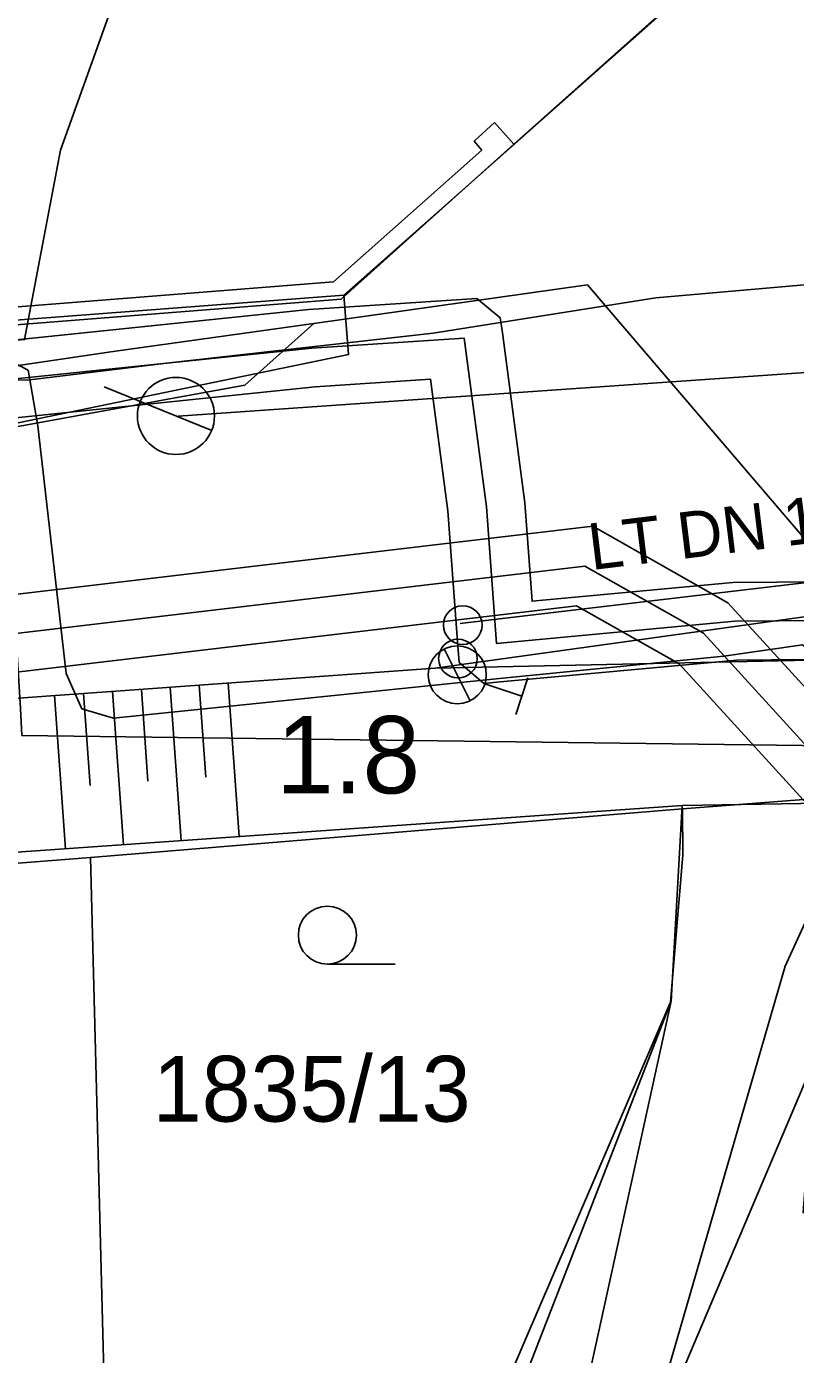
# Model space of a CAD drawing. Extents: x -781083 to -763634, y -1029516 to -1022695.
# Drawn here: x -765279.05 to -765259.17, y -1024370.44 to -1024336.12 of the extents above; entities that cross this region are included whole.
import ezdxf

# ---------------------------------------------------------------- set-up
doc = ezdxf.new("R2010")
doc.units = 0
for name, color, linetype in [('CETIN_chránička', 7, 'Continuous'), ('CETIN_nezaměřený', 7, 'Continuous'), ('CETIN_zaměřený', 7, 'Continuous'), ('GasNet_ochr. pásmo', 7, 'Continuous'), ('GasNet_plyn NTL', 7, 'Continuous'), ('GasNet_plyn STL', 7, 'Continuous'), ('Hranice parcel', 7, 'Continuous'), ('Parcelní čísla', 7, 'Continuous'), ('SVAS_kanalizace', 7, 'Continuous'), ('SVAS_vodovod', 7, 'Continuous'), ('Vnitřní kresba', 7, 'Continuous'), ('Vrstva 17', 7, 'Continuous'), ('Vrstva 41', 7, 'Continuous'), ('Vrstva 43', 7, 'Continuous'), ('Vrstva 48', 7, 'Continuous'), ('Vrstva 49', 7, 'Continuous'), ('Vrstva 51', 7, 'Continuous'), ('Značky kultur', 7, 'Continuous'), ('ČEZd_VN_podzemní', 7, 'Continuous')]:
    doc.layers.add(name, color=color, linetype=linetype)

# ---------------------------------------------------------------- blocks, each defined once
blk = doc.blocks.new('3.04')
at = {"layer": 'Značky kultur'}
blk.add_line((0.07, 0), (17.57, 0), dxfattribs=at)
blk.add_circle((0.07, 7.5), 7.5, dxfattribs=at)
blk = doc.blocks.new('C129_1')
at = {"layer": 'Vrstva 41'}
for p, q in [((-5.01, 17.59), (5, 17.58)), ((0.01, 17.59), (0, 7.51)), ((-5.31, -5.31), (5.31, 5.3))]:
    blk.add_line(p, q, dxfattribs=at)
blk.add_circle((0, 0.01), 7.5, dxfattribs=at)
blk = doc.blocks.new('C130_3')
at = {"layer": 'Vrstva 41'}
blk.add_circle((0, 0), 5, dxfattribs=at)
blk = doc.blocks.new('C138_6')
at = {"layer": 'Vrstva 43'}
blk.add_line((0, 20), (0, -9.96), dxfattribs=at)
blk.add_circle((0, 0), 9.96, dxfattribs=at)

msp = doc.modelspace()

# ---------------------------------------------------------------- linework, layer by layer
at = {"layer": 'CETIN_chránička'}
msp.add_lwpolyline([(-765278.76, -1024346.44), (-765278.03, -1024352.84)], dxfattribs=at)
at = {"layer": 'CETIN_nezaměřený'}
for points in [[(-765279.8, -1024344.26), (-765279.1, -1024344.21), (-765278.17, -1024339.31), (-765274.62, -1024329.4), (-765276.22, -1024328.8)], [(-765233.96, -1024367.52), (-765248.86, -1024367.26), (-765249.36, -1024367.26), (-765249.41, -1024354.76), (-765253.61, -1024354.77), (-765279.17, -1024354.44), (-765279.21, -1024353.74), (-765279.77, -1024344.76), (-765279.8, -1024344.26)]]:
    msp.add_lwpolyline(points, dxfattribs=at)
at = {"layer": 'CETIN_zaměřený'}
for points in [[(-765276.8, -1024353.99), (-765277.62, -1024353.75), (-765278.03, -1024352.84), (-765278.76, -1024346.44), (-765279.01, -1024345), (-765280.13, -1024344.42), (-765283.21, -1024344.71), (-765295.35, -1024345.6)], [(-765243.69, -1024369.24), (-765246.71, -1024370.2), (-765249.23, -1024369.66), (-765253.56, -1024368.44), (-765256.29, -1024367.55), (-765258.97, -1024366.77), (-765258.35, -1024358.4), (-765257.99, -1024355.91), (-765258.18, -1024352.73), (-765258.99, -1024352.1), (-765261.02, -1024352.39), (-765266.91, -1024352.98), (-765276.8, -1024353.99)]]:
    msp.add_lwpolyline(points, dxfattribs=at)
at = {"layer": 'GasNet_ochr. pásmo'}
for points in [[(-765296.108, -1024345.951), (-765271.754, -1024343.433), (-765267.806, -1024343.172), (-765267.412, -1024343.146), (-765266.801, -1024343.646), (-765266.749, -1024344.038), (-765266.165, -1024348.427), (-765265.978, -1024350.97), (-765260.791, -1024350.49), (-765256.229, -1024350.45), (-765255.23, -1024350.44), (-765255.005, -1024350.438), (-765254.597, -1024350.626), (-765254.453, -1024350.798), (-765251.47, -1024354.36), (-765251.133, -1024354.521), (-765240.171, -1024358.741), (-765236.98, -1024359.448), (-765232.08, -1024360.26), (-765229.243, -1024357.96), (-765220.744, -1024349.782)], [(-765219.956, -1024351.798), (-765227.917, -1024359.46), (-765231.52, -1024362.38), (-765237.36, -1024361.412), (-765240.749, -1024360.661), (-765251.927, -1024356.359), (-765252.733, -1024355.971), (-765252.953, -1024355.865), (-765253.246, -1024355.475), (-765253.271, -1024355.324), (-765255.683, -1024352.445), (-765256.211, -1024352.45), (-765260.689, -1024352.49), (-765266.808, -1024353.056), (-765267.226, -1024353.094), (-765267.546, -1024352.823), (-765267.866, -1024352.552), (-765267.897, -1024352.133), (-765268.155, -1024348.633), (-765268.608, -1024345.23), (-765271.586, -1024345.427), (-765296.406, -1024347.993)], [(-765281.55, -1024351.055), (-765264.412, -1024349.028), (-765260.919, -1024351.008), (-765256.965, -1024355.335), (-765255.329, -1024355.842), (-765247.192, -1024358.361), (-765246.248, -1024358.546), (-765246.208, -1024358.554), (-765231.828, -1024361.378), (-765230.549, -1024361.629), (-765223.59, -1024362.846), (-765218.997, -1024363.155)], [(-765218.903, -1024365.165), (-765223.83, -1024364.834), (-765230.913, -1024363.595), (-765232.214, -1024363.34), (-765246.596, -1024360.516), (-765246.636, -1024360.508), (-765247.682, -1024360.303), (-765255.921, -1024357.752), (-765258.075, -1024357.085), (-765262.181, -1024352.592), (-765264.828, -1024351.092), (-765281.35, -1024353.045)]]:
    msp.add_lwpolyline(points, dxfattribs=at)
at = {"layer": 'GasNet_plyn NTL'}
msp.add_lwpolyline([(-765185.486, -1024348.463), (-765200.18, -1024349.25), (-765208.725, -1024350.098), (-765209.45, -1024350.17), (-765218.22, -1024350.7), (-765219.37, -1024350.81), (-765220.35, -1024350.79), (-765228.58, -1024358.71), (-765231.8, -1024361.32), (-765237.17, -1024360.43), (-765240.46, -1024359.701), (-765251.53, -1024355.44), (-765252.3, -1024355.07), (-765252.33, -1024354.89), (-765255.22, -1024351.44), (-765256.22, -1024351.45), (-765260.74, -1024351.49), (-765266.9, -1024352.06), (-765267.16, -1024348.53), (-765267.74, -1024344.17), (-765271.67, -1024344.43), (-765296.257, -1024346.972)], dxfattribs=at)
at = {"layer": 'GasNet_plyn STL'}
msp.add_lwpolyline([(-765189.386, -1024346.571), (-765208.21, -1024348.24), (-765207.92, -1024349.91), (-765207.65, -1024363.32), (-765214.51, -1024363.44), (-765218.95, -1024364.16), (-765223.71, -1024363.84), (-765230.731, -1024362.612), (-765232.021, -1024362.359), (-765246.402, -1024359.535), (-765246.442, -1024359.527), (-765247.437, -1024359.332), (-765255.625, -1024356.797), (-765257.52, -1024356.21), (-765261.55, -1024351.8), (-765264.62, -1024350.06), (-765281.45, -1024352.05), (-765286.847, -1024352.499), (-765292.741, -1024352.989), (-765294.661, -1024353.149), (-765297.188, -1024353.359)], dxfattribs=at)
at = {"layer": 'Hranice parcel'}
for p, q in [((-765262.09, -1024356.34), (-765255.71, -1024355.84)), ((-765277.4, -1024357.59), (-765262.09, -1024356.34)), ((-765287.12, -1024358.38), (-765277.4, -1024357.59))]:
    msp.add_line(p, q, dxfattribs=at)
for points in [[(-765257.43, -1024331.1), (-765260.44, -1024333.79), (-765266.45, -1024339.16), (-765270.92, -1024343.16), (-765281.95, -1024344.03), (-765293.16, -1024344.91)], [(-765271.62, -1024343.79), (-765264.55, -1024342.79), (-765256.77, -1024351.88), (-765253.96, -1024351.5), (-765255.71, -1024355.84)], [(-765271.62, -1024343.79), (-765273.41, -1024345.39), (-765286.47, -1024347.76), (-765311.089, -1024349.588)], [(-765294.78, -1024345.04), (-765294.06, -1024347.03), (-765282.42, -1024345.34), (-765276.81, -1024344.52), (-765271.62, -1024343.79)], [(-765255.71, -1024355.84), (-765267.89, -1024384.53), (-765272.127, -1024397.764)], [(-765274.52, -1024389.5), (-765262.4, -1024361.33), (-765262.08, -1024357.53), (-765262.09, -1024356.34)], [(-765274.52, -1024389.5), (-765276.57, -1024389.53), (-765277.4, -1024357.59)]]:
    msp.add_lwpolyline(points, dxfattribs=at)
at = {"layer": 'SVAS_kanalizace'}
msp.add_lwpolyline([(-765275.13, -1024346.19), (-765247.256, -1024344.251), (-765227.391, -1024342.869), (-765224.66, -1024342.68)], dxfattribs=at)
at = {"layer": 'SVAS_vodovod'}
msp.add_lwpolyline([(-765250.1, -1024349.44), (-765255.019, -1024350.03), (-765267.839, -1024351.55)], dxfattribs=at)
at = {"layer": 'Vnitřní kresba'}
for p, q in [((-765266.95, -1024338.6), (-765267.48, -1024339.08)), ((-765266.45, -1024339.16), (-765266.95, -1024338.6)), ((-765267.48, -1024339.08), (-765267.28, -1024339.31)), ((-765267.28, -1024339.31), (-765271.11, -1024342.72)), ((-765271.11, -1024342.72), (-765281.78, -1024343.56))]:
    msp.add_line(p, q, dxfattribs=at)
at = {"layer": 'Vrstva 17'}
msp.add_line((-765266.345, -1024339.081), (-765260.356, -1024333.754), dxfattribs=at)
for points in [[(-765266.345, -1024339.081), (-765270.846, -1024343.058), (-765285.218, -1024344.154)], [(-765262.1, -1024356.254), (-765262.386, -1024361.308), (-765274.48, -1024392.413)]]:
    msp.add_lwpolyline(points, dxfattribs=at)
at = {"layer": 'Vrstva 48'}
for p, q in [((-765276.545, -1024357.263), (-765276.83, -1024353.301)), ((-765275.911, -1024355.625), (-765276.082, -1024353.248)), ((-765275.049, -1024357.158), (-765275.334, -1024353.194)), ((-765274.415, -1024355.52), (-765274.586, -1024353.14)), ((-765273.553, -1024357.054), (-765273.838, -1024353.086)), ((-765278.041, -1024357.367), (-765278.326, -1024353.409)), ((-765277.407, -1024355.731), (-765277.578, -1024353.355))]:
    msp.add_line(p, q, dxfattribs=at)
at = {"layer": 'Vrstva 49'}
for points in [[(-765253.558, -1024352.382), (-765268.485, -1024352.701)], [(-765268.485, -1024352.701), (-765283.331, -1024353.769)], [(-765257.498, -1024356.169), (-765262.1, -1024356.254), (-765283.002, -1024357.714)], [(-765270.318, -1024393.811), (-765266.533, -1024384.869), (-765259.437, -1024360.405), (-765257.498, -1024356.169)], [(-765262.386, -1024361.308), (-765262.1, -1024356.254)], [(-765274.48, -1024392.413), (-765268.773, -1024382.309), (-765265.313, -1024374.67), (-765262.386, -1024361.308)], [(-765274.48, -1024392.413), (-765262.386, -1024361.308)]]:
    msp.add_lwpolyline(points, dxfattribs=at)
at = {"layer": 'Vrstva 51'}
for points in [[(-765284.979, -1024347.539), (-765270.723, -1024344.592), (-765270.846, -1024343.058)], [(-765283.331, -1024353.769), (-765268.485, -1024352.701), (-765249.895, -1024350.117), (-765245.658, -1024350.908)]]:
    msp.add_lwpolyline(points, dxfattribs=at)
at = {"layer": 'ČEZd_VN_podzemní'}
msp.add_lwpolyline([(-765168.19, -1024337.56), (-765172.24, -1024337.59), (-765176.18, -1024337.66), (-765184.15, -1024337.97), (-765188.11, -1024337.86), (-765195.45, -1024338.12), (-765203.31, -1024339.25), (-765206.92, -1024339.32), (-765223.26, -1024341.24), (-765223.54, -1024341.17), (-765227.7, -1024341.2), (-765232.88, -1024341.47), (-765244.45, -1024342.64), (-765253.33, -1024342.3), (-765262.78, -1024343.13), (-765268.54, -1024344.04), (-765275.43, -1024344.82), (-765279.03, -1024345.26), (-765279.68, -1024345.25), (-765282.64, -1024345.64), (-765286.26, -1024346.45), (-765287.02, -1024346.69), (-765299.59, -1024348.02), (-765309.939, -1024348.848)], dxfattribs=at)

# ---------------------------------------------------------------- block references
at = {"layer": 'Vrstva 41'}
for name, p, xscale, yscale, rotation in [('C130_3', (-765267.772, -1024351.586), 0.09999999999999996, 0.09999999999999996, 7.913483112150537), ('C129_1', (-765267.914, -1024352.871), 0.09999999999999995, 0.09999999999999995, -108.26983467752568), ('C130_3', (-765267.896, -1024352.453), 0.09999999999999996, 0.09999999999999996, 7.913483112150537)]:
    msp.add_blockref(name, p, dxfattribs=dict(at, xscale=xscale, yscale=yscale, rotation=rotation))
at = {"layer": 'Vrstva 43', "xscale": 0.1, "yscale": 0.09999999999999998, "rotation": 67.94185044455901}
msp.add_blockref('C138_6', (-765275.187, -1024346.181), dxfattribs=at)
at = {"layer": 'Značky kultur', "xscale": 0.1, "yscale": 0.10000000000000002}
msp.add_blockref('3.04', (-765271.28, -1024360.35), dxfattribs=at)

# ---------------------------------------------------------------- texts
at = {"layer": 'Parcelní čísla'}
msp.add_text('1835/13', height=1.7, dxfattribs=at).set_placement((-765275.786, -1024364.42))
at = {"layer": 'SVAS_vodovod'}
msp.add_text('LT DN 100 ', height=1.2, rotation=7, dxfattribs=at).set_placement((-765264.446, -1024350.167))
at = {"layer": 'Vrstva 48'}
msp.add_text('1.8', height=2, dxfattribs=at).set_placement((-765272.594, -1024355.937))

doc.saveas('drawing.dxf')
